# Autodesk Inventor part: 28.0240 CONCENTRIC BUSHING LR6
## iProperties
Created: 2007-06
Part Number: 28.0240 CONCENTRIC BUSHING LR6
Material: Steel
Document SubType Name: Modeling
Designer: Andy Moles
Mass: 13.5624 g
Surface Area: 11.3295 cm^2
Volume: 1.72769 cm^3
Density: 7.85 g/cm^3
Author: Andy Moles
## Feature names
1. Base1
